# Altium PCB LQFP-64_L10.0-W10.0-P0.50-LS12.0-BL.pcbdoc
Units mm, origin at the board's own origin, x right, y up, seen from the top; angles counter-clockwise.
Board outline 25.6 x 25.6 mm, 2 copper layers (Top Layer, Bottom Layer), stack 0 mm thick; 1 components, 0 nets, 64 pads, 0 vias.
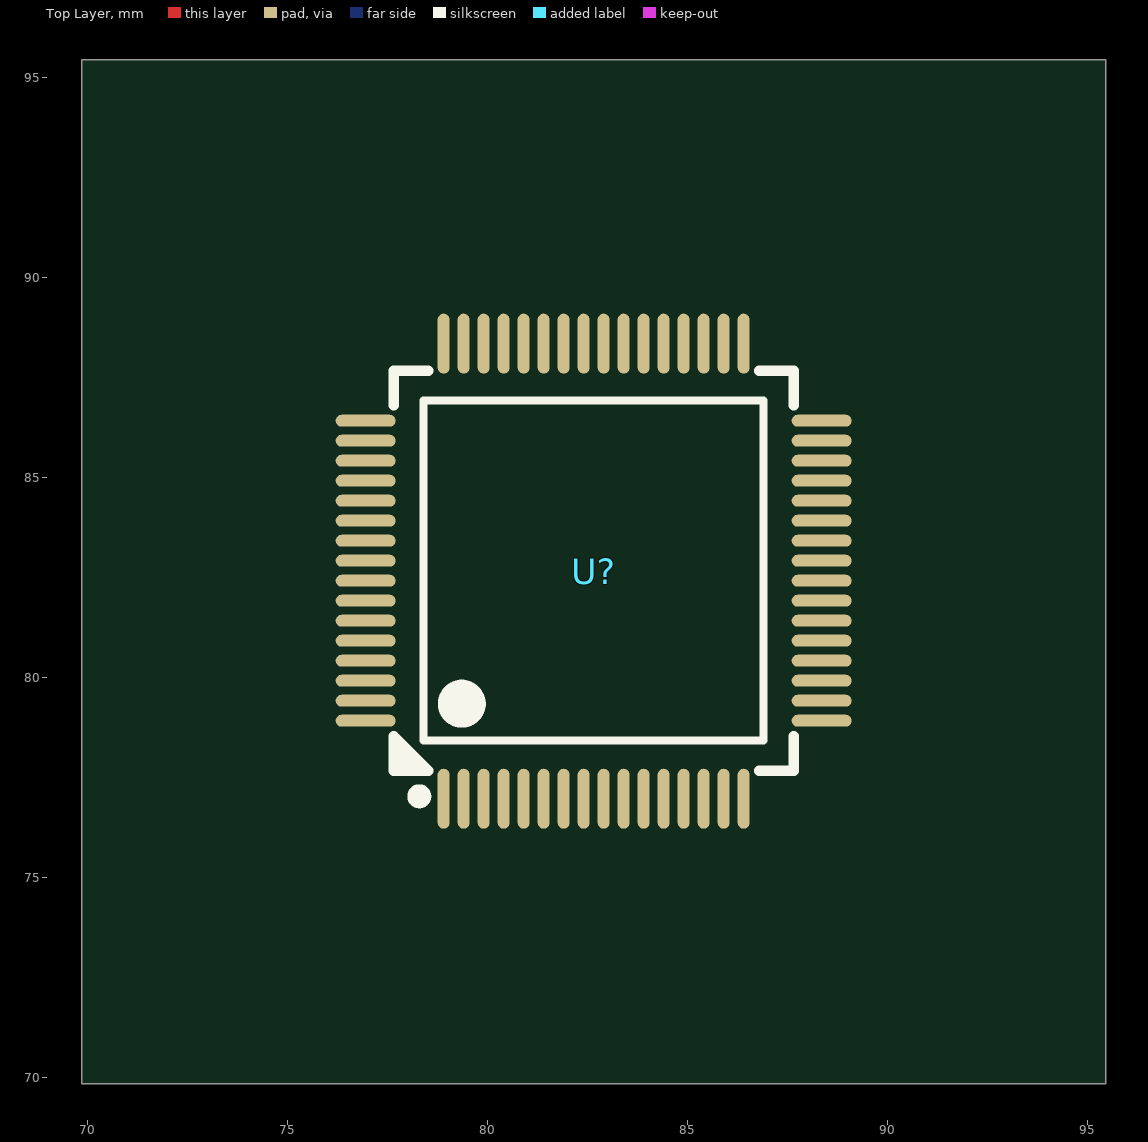
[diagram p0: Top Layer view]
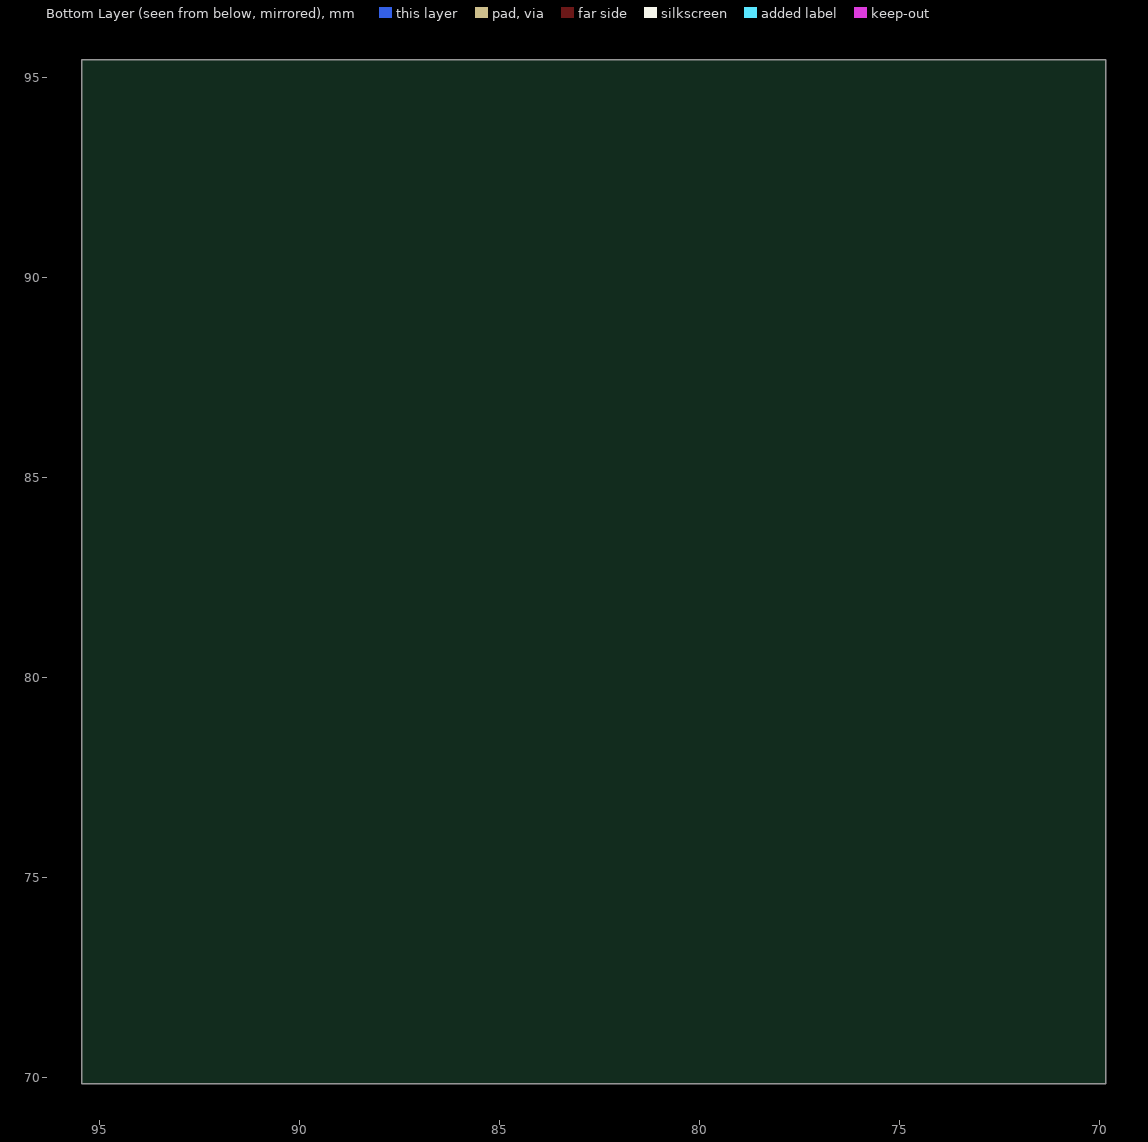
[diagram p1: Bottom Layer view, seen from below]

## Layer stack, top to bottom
Top Layer: signal copper (thickness not stored)
Bottom Layer: signal copper (thickness not stored)

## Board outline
95.45,69.85 69.85,69.85 69.85,95.447 95.45,95.447

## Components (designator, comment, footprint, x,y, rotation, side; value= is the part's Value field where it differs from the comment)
U? "" LQFP-64_L10.0-W10.0-P0.50-LS12.0-BL 82.65,82.658 r0 top

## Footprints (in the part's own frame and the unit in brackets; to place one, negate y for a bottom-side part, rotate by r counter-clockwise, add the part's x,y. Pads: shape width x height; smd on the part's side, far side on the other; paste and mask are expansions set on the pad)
LQFP-64_L10.0-W10.0-P0.50-LS12.0-BL [mm]
  oval 0.3x1.5 smd: 1(-3.75,-5.688) 2(-3.25,-5.688) 3(-2.75,-5.688) 4(-2.25,-5.688) 5(-1.75,-5.688) 6(-1.25,-5.688) 7(-0.75,-5.688) 8(-0.25,-5.688) 9(0.25,-5.688) 10(0.75,-5.688) 11(1.25,-5.688) 12(1.75,-5.688) 13(2.25,-5.688) 14(2.75,-5.688) 15(3.25,-5.688) 16(3.75,-5.688) 33(3.75,5.688) 34(3.25,5.688) 35(2.75,5.688) 36(2.25,5.688) 37(1.75,5.688) 38(1.25,5.688) 39(0.75,5.688) 40(0.25,5.688) 41(-0.25,5.688) 42(-0.75,5.688) 43(-1.25,5.688) 44(-1.75,5.688) 45(-2.25,5.688) 46(-2.75,5.688) 47(-3.25,5.688) 48(-3.75,5.688)
  oval 1.5x0.3 smd: 17(5.7,-3.738) 18(5.7,-3.238) 19(5.7,-2.738) 20(5.7,-2.238) 21(5.7,-1.738) 22(5.7,-1.238) 23(5.7,-0.738) 24(5.7,-0.238) 25(5.7,0.262) 26(5.7,0.762) 27(5.7,1.262) 28(5.7,1.762) 29(5.7,2.262) 30(5.7,2.762) 31(5.7,3.262) 32(5.7,3.762) 49(-5.7,3.762) 50(-5.7,3.262) 51(-5.7,2.762) 52(-5.7,2.262) 53(-5.7,1.762) 54(-5.7,1.262) 55(-5.7,0.762) 56(-5.7,0.262) 57(-5.7,-0.238) 58(-5.7,-0.738) 59(-5.7,-1.238) 60(-5.7,-1.738) 61(-5.7,-2.238) 62(-5.7,-2.738) 63(-5.7,-3.238) 64(-5.7,-3.738)
  silkscreen extent -5,-5.78 5,5.01

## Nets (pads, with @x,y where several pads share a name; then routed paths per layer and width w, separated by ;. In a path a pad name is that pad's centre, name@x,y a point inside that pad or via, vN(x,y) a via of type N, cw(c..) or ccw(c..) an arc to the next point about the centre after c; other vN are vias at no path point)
pads on no net: U?.1 U?.2 U?.3 U?.4 U?.5 U?.6 U?.7 U?.8 U?.9 U?.10 U?.11 U?.12 U?.13 U?.14 U?.15 U?.16 U?.17 U?.18 U?.19 U?.20 U?.21 U?.22 U?.23 U?.24 U?.25 U?.26 U?.27 U?.28 U?.29 U?.30 U?.31 U?.32 U?.33 U?.34 U?.35 U?.36 U?.37 U?.38 U?.39 U?.40 U?.41 U?.42 U?.43 U?.44 U?.45 U?.46 U?.47 U?.48 U?.49 U?.50 U?.51 U?.52 U?.53 U?.54 U?.55 U?.56 U?.57 U?.58 U?.59 U?.60 U?.61 U?.62 U?.63 U?.64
